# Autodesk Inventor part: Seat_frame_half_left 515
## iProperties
Shininess: 69.0
Length Units: 11269
Angle Units: 11279
Time Units: 11290
Mass Units: 11283
Length Display Precision: 3
Angle Display Precision: 2
Created: 2001-04
Part Number: Seat_frame_half_left 515
Material: Standard
Document SubType Name: Modellieren
Designer: dl
Density: 1 g/cm^3
Density: 0.0
Volumn: 0.0
Area: 0.0
PropertySet Name: Model Information
Control State: 0
Master: False
Checked Out: False
Author: dl
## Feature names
1. Sweep1
2. Extrusion1
3. Fillet1
4. Rectangular Pattern1
5. Extrusion2
6. Extrusion3
